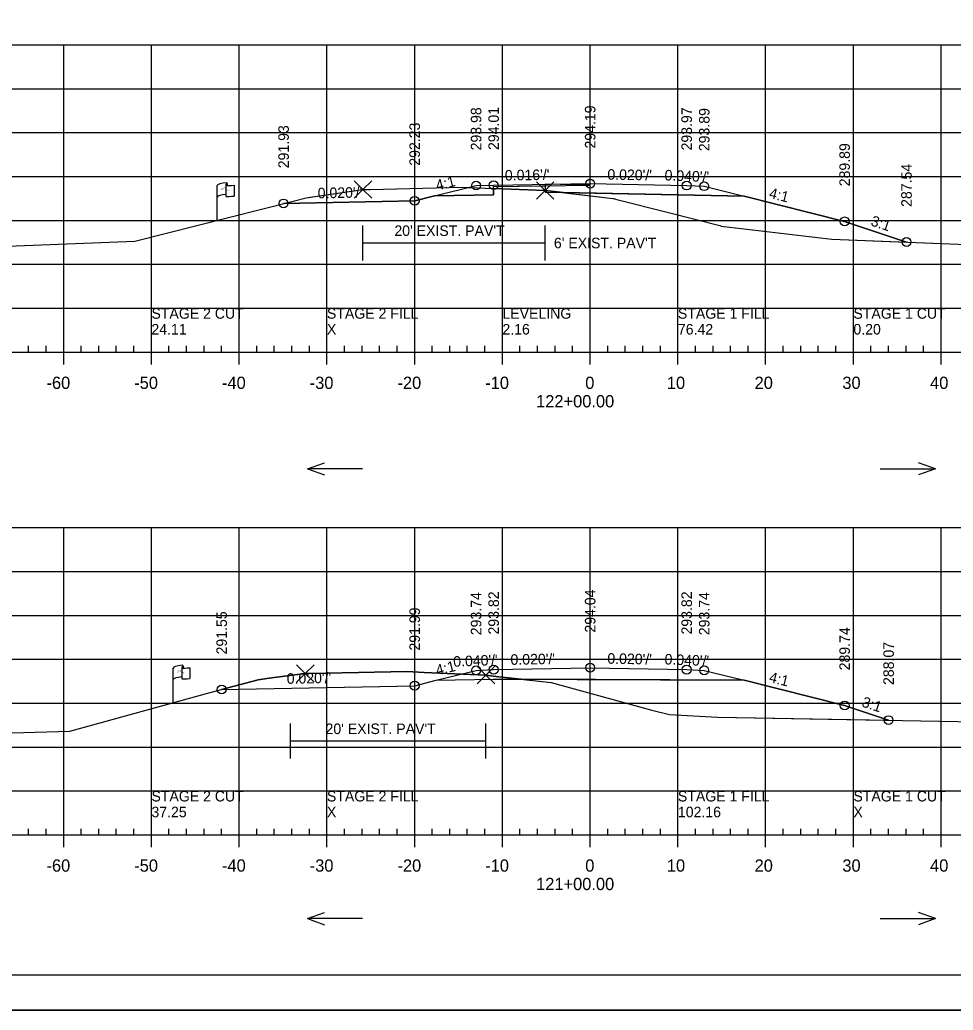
# Model space of a CAD drawing. Extents: x 1370843 to 1371177, y 380307 to 382654.
# Drawn here: x 1370948.7 to 1371055.1, y 382014.2 to 382127 of the extents above; entities that cross this region are included whole.
import ezdxf

# ---------------------------------------------------------------- set-up
doc = ezdxf.new("R2010")
doc.units = 0
for name, color, linetype in [('R_Alt Surface', 7, 'Continuous'), ('R_Axis', 7, 'Continuous'), ('R_Axis Annot', 7, 'Continuous'), ('R_Border', 7, 'Continuous'), ('R_Exist Surface', 7, 'Continuous'), ('R_Exist Surface Annot', 7, 'Continuous'), ('R_Fin Surface', 7, 'Continuous'), ('R_Fin Surface Annot', 7, 'Continuous'), ('R_Grid', 7, 'Continuous'), ('R_No Plot', 7, 'Continuous'), ('R_ROW', 7, 'Continuous'), ('R_Water Annot', 7, 'Continuous')]:
    doc.layers.add(name, color=color, linetype=linetype)

msp = doc.modelspace()

# ---------------------------------------------------------------- linework, layer by layer
at = {"layer": 'R_Alt Surface'}
for points in [[(1370995.96, 382106.95), (1371002.71, 382107.08), (1371002.71, 382108), (1371013.71, 382108.17), (1371008.58, 382108.28), (1371008.58, 382107.36), (1371031.25, 382106.91)], [(1370996.17, 382051.76), (1371002.71, 382051.89), (1371031.25, 382051.76)]]:
    msp.add_lwpolyline(points, dxfattribs=at)
at = {"layer": 'R_Axis'}
for p, q in [((1370949.71, 382089.15), (1370949.71, 382089.85)), ((1370951.71, 382089.15), (1370951.71, 382089.85)), ((1370955.71, 382089.15), (1370955.71, 382089.85)), ((1370957.71, 382089.15), (1370957.71, 382089.85)), ((1370959.71, 382089.15), (1370959.71, 382089.85)), ((1370961.71, 382089.15), (1370961.71, 382089.85)), ((1370965.71, 382089.15), (1370965.71, 382089.85)), ((1370967.71, 382089.15), (1370967.71, 382089.85)), ((1370969.71, 382089.15), (1370969.71, 382089.85)), ((1370971.71, 382089.15), (1370971.71, 382089.85)), ((1370975.71, 382089.15), (1370975.71, 382089.85)), ((1370977.71, 382089.15), (1370977.71, 382089.85)), ((1370979.71, 382089.15), (1370979.71, 382089.85)), ((1370981.71, 382089.15), (1370981.71, 382089.85)), ((1370985.71, 382089.15), (1370985.71, 382089.85)), ((1370987.71, 382089.15), (1370987.71, 382089.85)), ((1370989.71, 382089.15), (1370989.71, 382089.85)), ((1370991.71, 382089.15), (1370991.71, 382089.85)), ((1370995.71, 382089.15), (1370995.71, 382089.85)), ((1370997.71, 382089.15), (1370997.71, 382089.85)), ((1370999.71, 382089.15), (1370999.71, 382089.85)), ((1371001.71, 382089.15), (1371001.71, 382089.85)), ((1371005.71, 382089.15), (1371005.71, 382089.85)), ((1371007.71, 382089.15), (1371007.71, 382089.85)), ((1371009.71, 382089.15), (1371009.71, 382089.85)), ((1371011.71, 382089.15), (1371011.71, 382089.85)), ((1371015.71, 382089.15), (1371015.71, 382089.85)), ((1371017.71, 382089.15), (1371017.71, 382089.85)), ((1371019.71, 382089.15), (1371019.71, 382089.85)), ((1371021.71, 382089.15), (1371021.71, 382089.85)), ((1371025.71, 382089.15), (1371025.71, 382089.85)), ((1371027.71, 382089.15), (1371027.71, 382089.85)), ((1371029.71, 382089.15), (1371029.71, 382089.85)), ((1371031.71, 382089.15), (1371031.71, 382089.85)), ((1371035.71, 382089.15), (1371035.71, 382089.85)), ((1371037.71, 382089.15), (1371037.71, 382089.85)), ((1371039.71, 382089.15), (1371039.71, 382089.85)), ((1371041.71, 382089.15), (1371041.71, 382089.85)), ((1371045.71, 382089.15), (1371045.71, 382089.85)), ((1371047.71, 382089.15), (1371047.71, 382089.85)), ((1371049.71, 382089.15), (1371049.71, 382089.85)), ((1371051.71, 382089.15), (1371051.71, 382089.85)), ((1370868.71, 382089.15), (1371158.71, 382089.15)), ((1370953.71, 382087.75), (1370953.71, 382089.15)), ((1370963.71, 382087.75), (1370963.71, 382089.15)), ((1370973.71, 382087.75), (1370973.71, 382089.15)), ((1370983.71, 382087.75), (1370983.71, 382089.15)), ((1370993.71, 382087.75), (1370993.71, 382089.15)), ((1371003.71, 382087.75), (1371003.71, 382089.15)), ((1371013.71, 382087.75), (1371013.71, 382089.15)), ((1371023.71, 382087.75), (1371023.71, 382089.15)), ((1371033.71, 382087.75), (1371033.71, 382089.15)), ((1371043.71, 382087.75), (1371043.71, 382089.15)), ((1371053.71, 382087.75), (1371053.71, 382089.15)), ((1370868.71, 382034.15), (1371158.71, 382034.15)), ((1370949.71, 382034.15), (1370949.71, 382034.85)), ((1370951.71, 382034.15), (1370951.71, 382034.85)), ((1370953.71, 382032.75), (1370953.71, 382034.15)), ((1370955.71, 382034.15), (1370955.71, 382034.85)), ((1370957.71, 382034.15), (1370957.71, 382034.85)), ((1370959.71, 382034.15), (1370959.71, 382034.85)), ((1370961.71, 382034.15), (1370961.71, 382034.85)), ((1370963.71, 382032.75), (1370963.71, 382034.15)), ((1370965.71, 382034.15), (1370965.71, 382034.85)), ((1370967.71, 382034.15), (1370967.71, 382034.85)), ((1370969.71, 382034.15), (1370969.71, 382034.85)), ((1370971.71, 382034.15), (1370971.71, 382034.85)), ((1370973.71, 382032.75), (1370973.71, 382034.15)), ((1370975.71, 382034.15), (1370975.71, 382034.85)), ((1370977.71, 382034.15), (1370977.71, 382034.85)), ((1370979.71, 382034.15), (1370979.71, 382034.85)), ((1370981.71, 382034.15), (1370981.71, 382034.85)), ((1370983.71, 382032.75), (1370983.71, 382034.15)), ((1370985.71, 382034.15), (1370985.71, 382034.85)), ((1370987.71, 382034.15), (1370987.71, 382034.85)), ((1370989.71, 382034.15), (1370989.71, 382034.85)), ((1370991.71, 382034.15), (1370991.71, 382034.85)), ((1370993.71, 382032.75), (1370993.71, 382034.15)), ((1370995.71, 382034.15), (1370995.71, 382034.85)), ((1370997.71, 382034.15), (1370997.71, 382034.85)), ((1370999.71, 382034.15), (1370999.71, 382034.85)), ((1371001.71, 382034.15), (1371001.71, 382034.85)), ((1371003.71, 382032.75), (1371003.71, 382034.15)), ((1371005.71, 382034.15), (1371005.71, 382034.85)), ((1371007.71, 382034.15), (1371007.71, 382034.85)), ((1371009.71, 382034.15), (1371009.71, 382034.85)), ((1371011.71, 382034.15), (1371011.71, 382034.85)), ((1371013.71, 382032.75), (1371013.71, 382034.15)), ((1371015.71, 382034.15), (1371015.71, 382034.85)), ((1371017.71, 382034.15), (1371017.71, 382034.85)), ((1371019.71, 382034.15), (1371019.71, 382034.85)), ((1371021.71, 382034.15), (1371021.71, 382034.85)), ((1371023.71, 382032.75), (1371023.71, 382034.15)), ((1371025.71, 382034.15), (1371025.71, 382034.85)), ((1371027.71, 382034.15), (1371027.71, 382034.85)), ((1371029.71, 382034.15), (1371029.71, 382034.85)), ((1371031.71, 382034.15), (1371031.71, 382034.85)), ((1371033.71, 382032.75), (1371033.71, 382034.15)), ((1371035.71, 382034.15), (1371035.71, 382034.85)), ((1371037.71, 382034.15), (1371037.71, 382034.85)), ((1371039.71, 382034.15), (1371039.71, 382034.85)), ((1371041.71, 382034.15), (1371041.71, 382034.85)), ((1371043.71, 382032.75), (1371043.71, 382034.15)), ((1371045.71, 382034.15), (1371045.71, 382034.85)), ((1371047.71, 382034.15), (1371047.71, 382034.85)), ((1371049.71, 382034.15), (1371049.71, 382034.85)), ((1371051.71, 382034.15), (1371051.71, 382034.85)), ((1371053.71, 382032.75), (1371053.71, 382034.15))]:
    msp.add_line(p, q, dxfattribs=at)
at = {"layer": 'R_Border'}
msp.add_line((1371171.89, 382018.15), (1370855.71, 382018.15), dxfattribs=at)
at = {"layer": 'R_Exist Surface'}
for points in [[(1370921.23, 382100.29), (1370921.61, 382100.23), (1370937.63, 382100.82), (1370961.82, 382101.77), (1370979.86, 382106.36), (1370981.34, 382106.74), (1370981.8, 382106.81), (1370987.82, 382107.67), (1370988.64, 382107.69), (1370999.17, 382107.94), (1370999.85, 382107.91), (1371008.58, 382107.56), (1371016.29, 382106.64), (1371016.42, 382106.63), (1371016.6, 382106.58), (1371022.64, 382105.04), (1371028.47, 382103.56), (1371028.64, 382103.51), (1371029, 382103.47), (1371041.26, 382102.03), (1371071.02, 382100.83), (1371076.66, 382100.61)], [(1370913.3, 382044.81), (1370913.49, 382044.81), (1370925.46, 382045.14), (1370954.42, 382045.95), (1370970.4, 382050.35), (1370975.86, 382051.82), (1370977.13, 382051.98), (1370981.24, 382052.53), (1370983.59, 382052.58), (1370992.86, 382052.74), (1370994.81, 382052.65), (1371001.83, 382052.35), (1371003.31, 382052.16), (1371009.26, 382051.49), (1371020.73, 382048.37), (1371022.75, 382047.86), (1371028.21, 382047.57), (1371072.46, 382046.77)]]:
    msp.add_lwpolyline(points, dxfattribs=at)
at = {"layer": 'R_Exist Surface Annot'}
for p, q in [((1370987.82, 382099.58), (1370987.82, 382103.58)), ((1371008.58, 382099.58), (1371008.58, 382103.58)), ((1370987.82, 382101.58), (1371008.58, 382101.58)), ((1370979.54, 382042.84), (1370979.54, 382046.84)), ((1371001.83, 382042.84), (1371001.83, 382046.84)), ((1370979.54, 382044.84), (1371001.83, 382044.84))]:
    msp.add_line(p, q, dxfattribs=at)
at = {"layer": 'R_Fin Surface'}
for points in [[(1370978.77, 382106.09), (1370993.7, 382106.38), (1370993.71, 382106.38), (1370995.96, 382106.95), (1371000.71, 382108.13), (1371002.71, 382108.17), (1371013.71, 382108.34), (1371024.71, 382108.12), (1371026.71, 382108.04), (1371031.25, 382106.91), (1371042.71, 382104.04), (1371049.76, 382101.69)], [(1370971.71, 382050.7), (1370993.7, 382051.14), (1370993.71, 382051.14), (1370996.17, 382051.76), (1371000.71, 382052.89), (1371002.71, 382052.97), (1371013.71, 382053.19), (1371024.71, 382052.97), (1371026.71, 382052.89), (1371031.25, 382051.76), (1371042.71, 382048.89), (1371047.72, 382047.22)]]:
    msp.add_lwpolyline(points, dxfattribs=at)
at = {"layer": 'R_Grid'}
for p, q in [((1370868.71, 382124.15), (1371158.71, 382124.15)), ((1370953.71, 382089.15), (1370953.71, 382124.15)), ((1370963.71, 382089.15), (1370963.71, 382124.15)), ((1370973.71, 382089.15), (1370973.71, 382124.15)), ((1370983.71, 382089.15), (1370983.71, 382124.15)), ((1370993.71, 382089.15), (1370993.71, 382124.15)), ((1371003.71, 382089.15), (1371003.71, 382124.15)), ((1371013.71, 382089.15), (1371013.71, 382124.15)), ((1371023.71, 382089.15), (1371023.71, 382124.15)), ((1371033.71, 382089.15), (1371033.71, 382124.15)), ((1371043.71, 382089.15), (1371043.71, 382124.15)), ((1371053.71, 382089.15), (1371053.71, 382124.15)), ((1370868.71, 382119.15), (1371158.71, 382119.15)), ((1370868.71, 382114.15), (1371158.71, 382114.15)), ((1370868.71, 382109.15), (1371158.71, 382109.15)), ((1370868.71, 382104.15), (1371158.71, 382104.15)), ((1370868.71, 382099.15), (1371158.71, 382099.15)), ((1370868.71, 382094.15), (1371158.71, 382094.15)), ((1370868.71, 382089.15), (1371158.71, 382089.15)), ((1370868.71, 382069.15), (1371158.71, 382069.15)), ((1370953.71, 382034.15), (1370953.71, 382069.15)), ((1370963.71, 382034.15), (1370963.71, 382069.15)), ((1370973.71, 382034.15), (1370973.71, 382069.15)), ((1370983.71, 382034.15), (1370983.71, 382069.15)), ((1370993.71, 382034.15), (1370993.71, 382069.15)), ((1371003.71, 382034.15), (1371003.71, 382069.15)), ((1371013.71, 382034.15), (1371013.71, 382069.15)), ((1371023.71, 382034.15), (1371023.71, 382069.15)), ((1371033.71, 382034.15), (1371033.71, 382069.15)), ((1371043.71, 382034.15), (1371043.71, 382069.15)), ((1371053.71, 382034.15), (1371053.71, 382069.15)), ((1370868.71, 382064.15), (1371158.71, 382064.15)), ((1370868.71, 382059.15), (1371158.71, 382059.15)), ((1370868.71, 382054.15), (1371158.71, 382054.15)), ((1370868.71, 382049.15), (1371158.71, 382049.15)), ((1370868.71, 382044.15), (1371158.71, 382044.15)), ((1370868.71, 382039.15), (1371158.71, 382039.15)), ((1370868.71, 382034.15), (1371158.71, 382034.15))]:
    msp.add_line(p, q, dxfattribs=at)
at = {"layer": 'R_No Plot'}
msp.add_line((1370843.31, 382014.17), (1371176.64, 382014.17), dxfattribs=at)
for points in [[(1370843.3, 382227.51), (1371176.64, 382227.51), (1371176.64, 382014.17), (1370843.3, 382014.17)], [(1371089.63, 382223.61), (1371089.63, 382213.73), (1371125.36, 382213.73), (1371125.36, 382210.81), (1371148.56, 382210.81), (1371148.56, 382186.48), (1371171.89, 382186.48), (1371171.89, 382018.15), (1370855.71, 382018.15), (1370855.71, 382223.61)], [(1371002.71, 382107.8), (1371002.71, 382107.08), (1370995.96, 382106.95), (1370993.71, 382106.38), (1370978.77, 382106.09), (1370979.86, 382106.36), (1370981.34, 382106.74), (1370987.82, 382107.67), (1370988.64, 382107.69), (1370999.17, 382107.94), (1370999.85, 382107.91)], [(1371002.71, 382107.8), (1371002.71, 382108), (1371008.58, 382108.09), (1371008.58, 382107.56)], [(1371008.58, 382107.56), (1371008.58, 382107.36), (1371010.62, 382107.32)], [(1371010.62, 382107.32), (1371016.29, 382106.64), (1371016.42, 382106.63), (1371016.6, 382106.58), (1371022.64, 382105.04), (1371028.47, 382103.56), (1371028.64, 382103.51), (1371029, 382103.47), (1371041.26, 382102.03), (1371049.76, 382101.69), (1371042.71, 382104.04), (1371031.25, 382106.91)], [(1370971.71, 382050.7), (1370993.71, 382051.14), (1370996.17, 382051.76), (1371002.71, 382051.89), (1371005.86, 382051.87), (1371003.31, 382052.16), (1371001.83, 382052.35), (1370994.81, 382052.65), (1370992.86, 382052.74), (1370983.59, 382052.58), (1370981.24, 382052.53), (1370977.13, 382051.98), (1370975.86, 382051.82)], [(1371005.86, 382051.87), (1371009.26, 382051.49), (1371020.73, 382048.37), (1371022.75, 382047.86), (1371028.21, 382047.57), (1371047.72, 382047.22), (1371042.71, 382048.89), (1371031.25, 382051.76)]]:
    msp.add_lwpolyline(points, close=True, dxfattribs=at)
for points in [[(1370987.82, 382107.67), (1370986.82, 382108.67), (1370987.82, 382107.67), (1370986.82, 382106.67), (1370987.82, 382107.67), (1370988.82, 382106.67), (1370987.82, 382107.67), (1370988.82, 382108.67)], [(1371008.58, 382107.56), (1371007.58, 382108.56), (1371008.58, 382107.56), (1371007.58, 382106.56), (1371008.58, 382107.56), (1371009.58, 382106.56), (1371008.58, 382107.56), (1371009.58, 382108.56)], [(1370981.24, 382052.53), (1370980.24, 382053.53), (1370981.24, 382052.53), (1370980.24, 382051.53), (1370981.24, 382052.53), (1370982.24, 382051.53), (1370981.24, 382052.53), (1370982.24, 382053.53)], [(1371001.83, 382052.35), (1371000.83, 382053.35), (1371001.83, 382052.35), (1371000.83, 382051.35), (1371001.83, 382052.35), (1371002.83, 382051.35), (1371001.83, 382052.35), (1371002.83, 382053.35)]]:
    msp.add_lwpolyline(points, dxfattribs=at)
for centre in [(1371000.71, 382108.13), (1371002.71, 382108.17), (1371013.71, 382108.34), (1371024.71, 382108.12), (1371026.71, 382108.04), (1370978.77, 382106.09), (1370993.71, 382106.38), (1371042.71, 382104.04), (1371049.76, 382101.69), (1371000.71, 382052.89), (1371002.71, 382052.97), (1371013.71, 382053.19), (1371024.71, 382052.97), (1371026.71, 382052.89), (1370971.71, 382050.7), (1370993.71, 382051.14), (1371042.71, 382048.89), (1371047.72, 382047.22)]:
    msp.add_circle(centre, 0.5, dxfattribs=at)
at = {"layer": 'R_ROW'}
for p, q in [((1370971.2, 382104.16), (1370971.2, 382108.11)), ((1370972.19, 382108.2), (1370972.19, 382108.19)), ((1370972.19, 382108.19), (1370972.19, 382106.96)), ((1370972.36, 382108.36), (1370972.36, 382108.12)), ((1370973.13, 382108.16), (1370973.13, 382106.92)), ((1370967.17, 382053.23), (1370967.17, 382053.21)), ((1370967.17, 382053.21), (1370967.17, 382051.99)), ((1370967.33, 382053.38), (1370967.33, 382053.14)), ((1370968.1, 382053.19), (1370968.1, 382051.95)), ((1370966.17, 382049.18), (1370966.17, 382053.13))]:
    msp.add_line(p, q, dxfattribs=at)
for centre, radius, start, end in [((1370972.27, 382108.2), 0.078, 88.6458, 274.2828), ((1370972.28, 382108.36), 0.0783, 263.0712, 93.9564), ((1370972.27, 382106.96), 0.0783, 180, 273.9564), ((1370967.24, 382053.23), 0.078, 88.6458, 274.2828), ((1370967.26, 382053.38), 0.0783, 263.0712, 93.9564), ((1370967.25, 382051.99), 0.0783, 180, 273.9564)]:
    msp.add_arc(centre, radius, start, end, dxfattribs=at)
for centre, major_axis, ratio, start_param, end_param in [((1370972.78, 382108.15), (-1.58, -0.04), 0.19887, 5.030368, 6.283185), ((1370973.49, 382108.27), (-1.23, -0.13), 0.052933, 0.159456, 1.268315), ((1370972.77, 382106.83), (-1.58, -0.04), 0.19887, 5.083035, 6.194897), ((1370973.49, 382107.03), (-1.23, -0.13), 0.052933, 0.159456, 1.268315), ((1370967.75, 382053.18), (-1.58, -0.04), 0.19887, 5.030368, 6.283185), ((1370968.46, 382053.29), (-1.23, -0.13), 0.052933, 0.159456, 1.268315), ((1370967.75, 382051.86), (-1.58, -0.04), 0.19887, 5.083035, 6.194897), ((1370968.46, 382052.05), (-1.23, -0.13), 0.052933, 0.159456, 1.268315)]:
    msp.add_ellipse(centre, major_axis=major_axis, ratio=ratio, start_param=start_param, end_param=end_param, dxfattribs=at)
at = {"layer": 'R_Water Annot'}
for p, q in [((1370981.5, 382075.85), (1370983.42, 382076.55)), ((1370987.78, 382075.85), (1370981.5, 382075.85)), ((1370981.5, 382075.85), (1370983.42, 382075.15)), ((1371046.77, 382075.85), (1371053.05, 382075.85)), ((1371053.05, 382075.85), (1371051.13, 382076.55)), ((1371053.05, 382075.85), (1371051.13, 382075.15)), ((1370981.5, 382024.6), (1370983.42, 382025.3)), ((1371053.05, 382024.6), (1371051.13, 382025.3)), ((1370987.78, 382024.6), (1370981.5, 382024.6)), ((1370981.5, 382024.6), (1370983.42, 382023.9)), ((1371046.77, 382024.6), (1371053.05, 382024.6)), ((1371053.05, 382024.6), (1371051.13, 382023.9))]:
    msp.add_line(p, q, dxfattribs=at)

# ---------------------------------------------------------------- texts
at = {"layer": 'R_Axis Annot'}
for s, p in [('-60', (1370951.75, 382084.95)), ('-50', (1370961.75, 382084.95)), ('-40', (1370971.75, 382084.95)), ('-30', (1370981.75, 382084.95)), ('-20', (1370991.75, 382084.95)), ('-10', (1371001.75, 382084.95)), ('0', (1371013.15, 382084.95)), ('10', (1371022.45, 382084.95)), ('20', (1371032.45, 382084.95)), ('30', (1371042.45, 382084.95)), ('40', (1371052.45, 382084.95)), ('122+00.00', (1371007.55, 382082.85)), ('-60', (1370951.75, 382029.95)), ('-50', (1370961.75, 382029.95)), ('-40', (1370971.75, 382029.95)), ('-30', (1370981.75, 382029.95)), ('-20', (1370991.75, 382029.95)), ('-10', (1371001.75, 382029.95)), ('0', (1371013.15, 382029.95)), ('10', (1371022.45, 382029.95)), ('20', (1371032.45, 382029.95)), ('30', (1371042.45, 382029.95)), ('40', (1371052.45, 382029.95)), ('121+00.00', (1371007.55, 382027.85))]:
    msp.add_text(s, height=1.4, dxfattribs=at).set_placement(p)
at = {"layer": 'R_Exist Surface Annot'}
for p in [(1370991.4, 382102.38), (1370983.55, 382045.63)]:
    msp.add_text("20' EXIST. PAV'T", height=1.2, dxfattribs=at).set_placement(p)
at = {"layer": 'R_Fin Surface Annot'}
for s, rotation, p in [('293.98', 90, (1371001.31, 382112.13)), ('294.01', 90, (1371003.31, 382112.17)), ('294.19', 90, (1371014.31, 382112.34)), ('293.97', 90, (1371025.31, 382112.12)), ('293.89', 90, (1371027.31, 382112.04)), ('292.23', 90, (1370994.31, 382110.38)), ('291.93', 90, (1370979.37, 382110.09)), ('289.89', 90, (1371043.31, 382108.04)), ("0.016'/'", 0.9083, (1371004, 382108.69)), ("0.020'/'", 358.8542, (1371015.66, 382108.8)), ("0.040'/'", 357.7094, (1371022.17, 382108.72)), ('287.54', 90, (1371050.36, 382105.69)), ('4:1', 14.0362, (1370996.28, 382107.54)), ("0.020'/'", 1.1458, (1370982.67, 382106.66)), ('4:1', 345.9638, (1371034.02, 382106.73)), ('3:1', 341.5651, (1371045.6, 382103.6)), ('293.74', 90, (1371001.31, 382056.89)), ('293.82', 90, (1371003.31, 382056.97)), ('294.04', 90, (1371014.31, 382057.19)), ('293.82', 90, (1371025.31, 382056.97)), ('293.74', 90, (1371027.31, 382056.89)), ('291.99', 90, (1370994.31, 382055.14)), ('291.55', 90, (1370972.31, 382054.7)), ('289.74', 90, (1371043.31, 382052.89)), ('288.07', 90, (1371048.32, 382051.22)), ("0.040'/'", 2.2906, (1370998.13, 382053.29)), ("0.020'/'", 1.1458, (1371004.64, 382053.51)), ("0.020'/'", 358.8542, (1371015.66, 382053.65)), ("0.040'/'", 357.7094, (1371022.17, 382053.57)), ('4:1', 14.0362, (1370996.28, 382052.3)), ("0.020'/'", 1.1458, (1370979.14, 382051.35)), ('4:1', 345.9638, (1371034.02, 382051.58)), ('3:1', 341.5651, (1371044.58, 382048.79))]:
    msp.add_text(s, height=1.2, rotation=rotation, dxfattribs=at).set_placement(p)
at = {"layer": 'R_No Plot'}
for s, p in [("6' EXIST. PAV'T", (1371009.58, 382100.98)), ('STAGE 2 CUT', (1370963.71, 382092.95)), ('STAGE 2 FILL', (1370983.71, 382092.95)), ('LEVELING', (1371003.71, 382092.95)), ('STAGE 1 FILL', (1371023.71, 382092.95)), ('STAGE 1 CUT', (1371043.71, 382092.95)), ('24.11', (1370963.71, 382091.15)), ('X', (1370983.71, 382091.15)), ('2.16', (1371003.71, 382091.15)), ('76.42', (1371023.71, 382091.15)), ('0.20', (1371043.71, 382091.15)), ('STAGE 2 CUT', (1370963.71, 382037.95)), ('STAGE 2 FILL', (1370983.71, 382037.95)), ('STAGE 1 FILL', (1371023.71, 382037.95)), ('STAGE 1 CUT', (1371043.71, 382037.95)), ('37.25', (1370963.71, 382036.15)), ('102.16', (1371023.71, 382036.15)), ('X', (1370983.71, 382036.15)), ('X', (1371043.71, 382036.15))]:
    msp.add_text(s, height=1.2, dxfattribs=at).set_placement(p)
at = {"layer": 'R_ROW'}
for s, height, rotation, p in [('R ', 0.2, 9.9884, (1370971.72, 382107.61)), (' O', 0.2, 9.9884, (1370971.86, 382107.65)), ('W', 0.2, 351.1788, (1370972.19, 382107.48)), ('DWB 11-9-07', 0.001, 90, (1370972.36, 382108.12)), ('DWB 11-9-07', 0.001, 5.0717, (1370973.12, 382106.92)), ('DWB 11-9-07', 0.001, 90, (1370971.2, 382104.16)), ('R ', 0.2, 9.9884, (1370966.69, 382052.63)), (' O', 0.2, 9.9884, (1370966.84, 382052.68)), ('W', 0.2, 351.1788, (1370967.17, 382052.51)), ('DWB 11-9-07', 0.001, 90, (1370967.33, 382053.14)), ('DWB 11-9-07', 0.001, 5.0717, (1370968.09, 382051.95)), ('DWB 11-9-07', 0.001, 90, (1370966.17, 382049.18))]:
    msp.add_text(s, height=height, rotation=rotation, dxfattribs=at).set_placement(p)

doc.saveas('drawing.dxf')
